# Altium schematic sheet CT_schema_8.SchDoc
size 287 x 160 mm
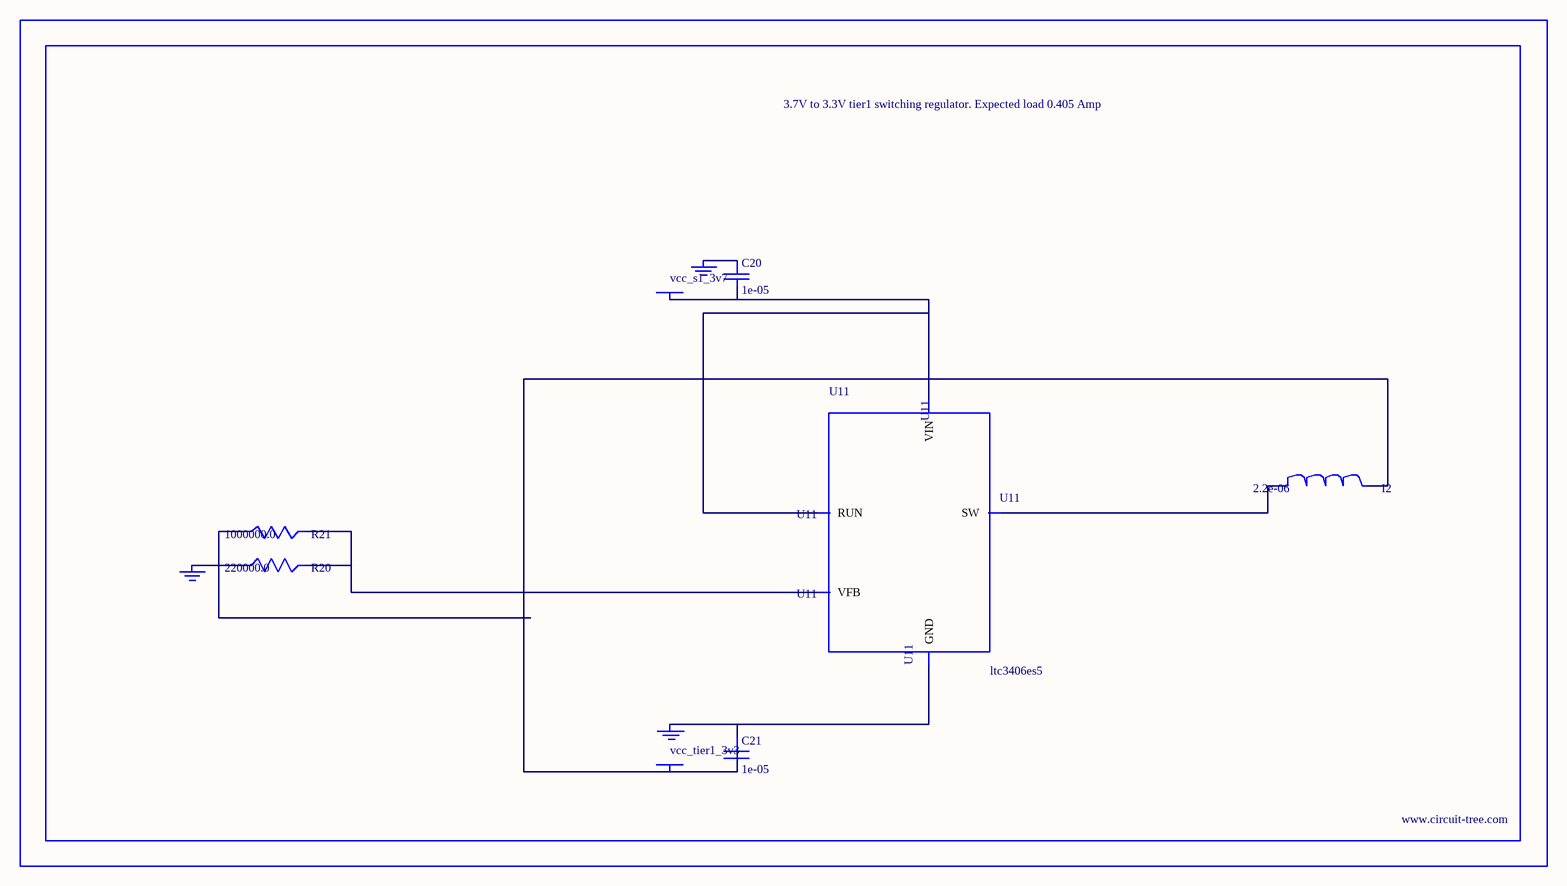
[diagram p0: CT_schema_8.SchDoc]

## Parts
BORDER7  (no value)
C20  1e-05  [C0805]
C21  1e-05  [C0805]
GND_INSTANCE_7_0  (no value)
GND_INSTANCE_7_1  (no value)
GND_INSTANCE_7_2  (no value)
I2  2.2e-06  [L0805]
POWER_INSTANCE_7_0  vcc_tier1_3v3
POWER_INSTANCE_7_1  vcc_s1_3v7
R20  220000.0  [R0603]
R21  1000000.0  [R0603]
U11  ltc3406es5  [TSOT-23-5]

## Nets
NetC20_1: C20.1 GND_INSTANCE_7_1.0(GND)
NetC20_2: C20.2 POWER_INSTANCE_7_1.0(PWR) U11.1(RUN) U11.4(VIN)
NetC21_1: C21.1 GND_INSTANCE_7_0.0(GND) U11.2(GND)
NetC21_2: C21.2 I2.2 POWER_INSTANCE_7_0.0(PWR) R21.1
NetGND_INSTANCE_7_2_0: GND_INSTANCE_7_2.0(GND) R20.1
NetI2_1: I2.1 U11.3(SW)
NetR20_2: R20.2 R21.2 U11.5(VFB)

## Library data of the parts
BORDER7 = BORDER_PAGE7
C20 C21 = C0805C106K8RACTU
GND_INSTANCE_7_0-GND_INSTANCE_7_2 = GND
I2 = L0805C2R2MDWIT
POWER_INSTANCE_7_0 POWER_INSTANCE_7_1 = PWR
R20 = RC0603JR-07220KL
R21 = RC0603JR-071ML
